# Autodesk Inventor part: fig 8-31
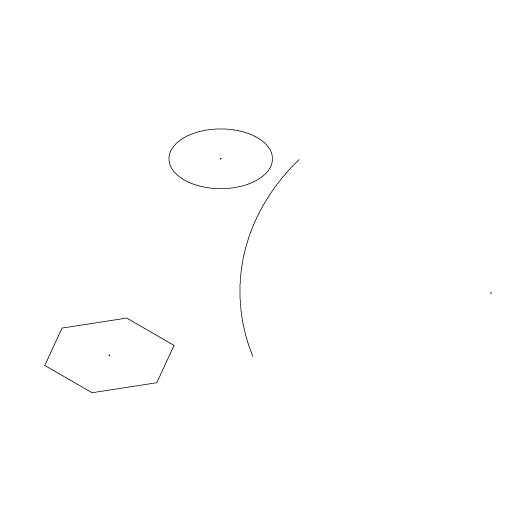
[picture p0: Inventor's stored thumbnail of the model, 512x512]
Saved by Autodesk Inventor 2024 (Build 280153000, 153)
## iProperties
Shininess: 77.0
Angle Display Precision: 2
Document Length Units: 11269
Document Angle Units: 11279
Document Time Units: 11290
Document Mass Units: 11283
Document Length Units Precision: 3
Document Angle Units Precision: 2
Created: 2001-12
Part Number: fig 8-31
Document SubType Name: Modeling
Designer: CADSoft
Density: 1 g/cm^3
Material: Generic
Appearance: Default
Density: 0.0
Volumn: 0.0
Area: 0.0
PropertySet Name: Model Information
Control State: 0
Master: False
Checked Out: False
Author: CADSoft
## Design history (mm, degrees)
workplane "Work Plane3"
workplane "Work Plane4"
sketch "Sketch12"
  geometry: L1 (0, 10.598)-(9.178, -5.299); L2 (9.178, -5.299)-(-9.178, -5.299); L3 (-9.178, -5.299)-(0, 10.598); 1 further point
  constraints: 6 end point, 5 other
workplane "Work Plane5"
workplane "Work Plane6"
workplane "Work Plane7"
sketch "Sketch16"
  geometry: A1 r 72.799 centre (23.007, 110.594) between (0, 41.527) and (70, 54.995); 1 further point
  constraints: 2 point on circle, 1 centre point
body "Solid1"
sketch "Sketch1"
  geometry: L1 (19.387, 0)-(9.693, -16.79); L2 (9.693, -16.79)-(-9.693, -16.79); L3 (-9.693, -16.79)-(-19.387, 0); L4 (-19.387, 0)-(-9.693, 16.79); L5 (-9.693, 16.79)-(9.693, 16.79); L6 (9.693, 16.79)-(19.387, 0); 1 further point
  constraints: 12 end point, 11 other
sketch "Sketch2"
  geometry: C1 r 15 at (23.06, 22.535)
  constraints: 1 centre point
